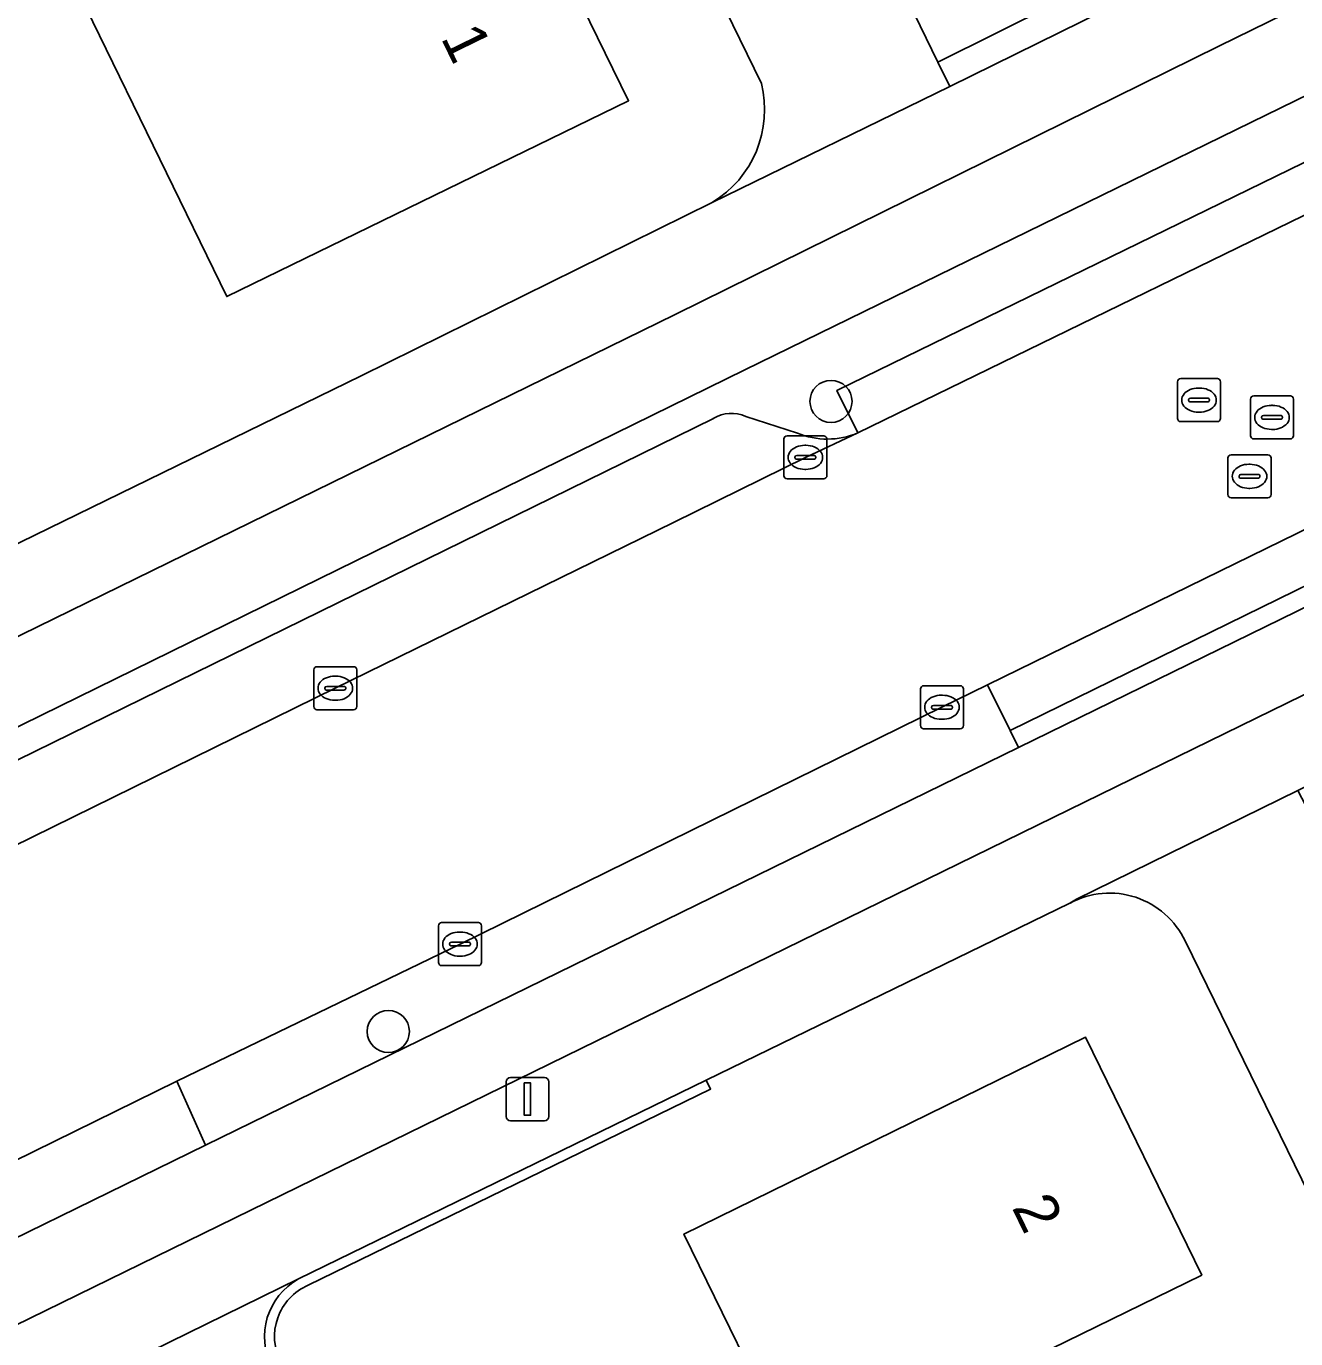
# Model space of a CAD drawing. Extents: x 160455 to 162082, y 388339 to 389736.
# Drawn here: x 160724.31 to 160753.79, y 388806.27 to 388836.74 of the extents above; entities that cross this region are included whole.
import ezdxf

# ---------------------------------------------------------------- set-up
doc = ezdxf.new("R2010")
doc.units = 0
for name, color, linetype in [('IMGEO_Berm_groen', 7, 'Continuous'), ('IMGEO_Boom', 7, 'Continuous'), ('IMGEO_Erf', 7, 'Continuous'), ('IMGEO_Fietspad_gesloten', 7, 'Continuous'), ('IMGEO_Fietspad_open', 7, 'Continuous'), ('IMGEO_Kolk', 7, 'Continuous'), ('IMGEO_Lichtmast', 7, 'Continuous'), ('IMGEO_Muur', 7, 'Continuous'), ('IMGEO_Pand', 7, 'Continuous'), ('IMGEO_Pand_nummerreeks', 7, 'Continuous'), ('IMGEO_Parkeervlak_open', 7, 'Continuous'), ('IMGEO_Rijbaan_lokaal_gesloten', 7, 'Continuous'), ('IMGEO_Rioolput', 7, 'Continuous'), ('IMGEO_Verkeerseiland_open', 7, 'Continuous'), ('IMGEO_Voetpad_open', 7, 'Continuous')]:
    doc.layers.add(name, color=color, linetype=linetype)

msp = doc.modelspace()

# ---------------------------------------------------------------- linework, layer by layer
at = {"layer": 'IMGEO_Berm_groen'}
msp.add_lwpolyline([(160747.35, 388819.997), (160747.16, 388820.393), (160746.633, 388821.448), (160745.575, 388820.932), (160734.385, 388815.434), (160727.808, 388812.252), (160728.479, 388810.767)], close=True, dxfattribs=at)
at = {"layer": 'IMGEO_Boom'}
for centre in [(160742.999, 388828.032), (160732.72, 388813.404)]:
    msp.add_circle(centre, 0.489, dxfattribs=at)
at = {"layer": 'IMGEO_Erf'}
for points in [[(160741.386, 388835.41), (160711.402, 388896.761)], [(160735.599, 388840.535), (160738.298, 388835.011), (160728.968, 388830.464), (160725.86, 388836.841)], [(160722.854, 388824.118), (160732.091, 388828.627), (160740.243, 388832.65)], [(160748.547, 388816.384), (160740.102, 388812.273), (160740.203, 388812.065), (160730.861, 388807.511)], [(160798.94, 388717.887), (160783.242, 388750), (160751.22, 388815.507)], [(160740.569, 388802.888), (160742.068, 388803.624), (160739.584, 388808.699), (160748.904, 388813.275), (160751.608, 388807.748), (160747.062, 388805.524), (160748.312, 388802.966), (160749.688, 388800.152), (160754.231, 388802.38)]]:
    msp.add_lwpolyline(points, dxfattribs=at)
for centre, radius, start, end in [((160738.931, 388834.81), 2.527, 301.27, 13.7381), ((160749.468, 388814.678), 1.938, 25.3141, 118.357), ((160731.374, 388806.321), 1.296, 113.309, 207.7642)]:
    msp.add_arc(centre, radius, start, end, dxfattribs=at)
at = {"layer": 'IMGEO_Fietspad_gesloten'}
msp.add_lwpolyline([(160935.958, 388926.245), (160935.472, 388926.041), (160929.623, 388923.115), (160929.542, 388923.081), (160924.149, 388920.448), (160820.314, 388869.678), (160812.524, 388865.895), (160804.151, 388861.828), (160752.018, 388836.29), (160739.38, 388830.051), (160696.889, 388809.242), (160688.114, 388804.953), (160688.97, 388803.215), (160707.492, 388812.318), (160716.69, 388816.833), (160716.639, 388816.936), (160723.758, 388820.418), (160723.804, 388820.325), (160740.999, 388828.766), (160761.388, 388838.743), (160804.958, 388860.084), (160820.353, 388867.581)], dxfattribs=at)
at = {"layer": 'IMGEO_Fietspad_open'}
msp.add_lwpolyline([(160814.94, 388853.077), (160807.357, 388849.403), (160800.037, 388845.82), (160791.543, 388841.683), (160784.31, 388838.109), (160774.906, 388833.514), (160767.644, 388829.959), (160760.974, 388826.661), (160747.35, 388819.997), (160728.479, 388810.767), (160721.36, 388807.285), (160701.311, 388797.443), (160693.649, 388793.713), (160694.449, 388792.087), (160749.247, 388818.903), (160815.775, 388851.461)], dxfattribs=at)
at = {"layer": 'IMGEO_Kolk'}
for p, q in [((160741.903, 388826.308), (160741.903, 388827.16)), ((160741.978, 388827.234), (160742.83, 388827.234)), ((160742.904, 388827.16), (160742.904, 388826.308)), ((160742.391, 388827.014), (160742.416, 388827.014)), ((160742.162, 388826.728), (160742.162, 388826.74)), ((160742.6, 388826.691), (160742.202, 388826.691)), ((160742.205, 388826.777), (160742.603, 388826.777)), ((160742.646, 388826.74), (160742.646, 388826.728)), ((160742.414, 388826.454), (160742.389, 388826.454)), ((160742.83, 388826.234), (160741.978, 388826.234)), ((160730.989, 388820.947), (160730.989, 388821.799)), ((160731.064, 388821.873), (160731.916, 388821.873)), ((160731.99, 388821.799), (160731.99, 388820.947)), ((160731.248, 388821.367), (160731.248, 388821.379)), ((160731.291, 388821.416), (160731.689, 388821.416)), ((160731.477, 388821.653), (160731.502, 388821.653)), ((160731.732, 388821.379), (160731.732, 388821.367)), ((160745.149, 388821.431), (160746.001, 388821.431)), ((160731.686, 388821.33), (160731.288, 388821.33)), ((160731.5, 388821.093), (160731.475, 388821.093)), ((160745.074, 388820.505), (160745.074, 388821.357)), ((160745.562, 388821.211), (160745.587, 388821.211)), ((160746.075, 388821.357), (160746.075, 388820.505)), ((160731.916, 388820.873), (160731.064, 388820.873)), ((160745.333, 388820.925), (160745.333, 388820.937)), ((160745.771, 388820.888), (160745.373, 388820.888)), ((160745.376, 388820.974), (160745.774, 388820.974)), ((160745.817, 388820.937), (160745.817, 388820.925)), ((160745.585, 388820.651), (160745.56, 388820.651)), ((160746.001, 388820.431), (160745.149, 388820.431)), ((160733.959, 388815.933), (160734.811, 388815.933)), ((160733.884, 388815.007), (160733.884, 388815.859)), ((160734.372, 388815.713), (160734.397, 388815.713)), ((160734.885, 388815.859), (160734.885, 388815.007)), ((160734.143, 388815.427), (160734.143, 388815.439)), ((160734.581, 388815.39), (160734.183, 388815.39)), ((160734.186, 388815.476), (160734.584, 388815.476)), ((160734.627, 388815.439), (160734.627, 388815.427)), ((160734.395, 388815.153), (160734.37, 388815.153)), ((160734.811, 388814.933), (160733.959, 388814.933))]:
    msp.add_line(p, q, dxfattribs=at)
for points in [[(160741.903, 388826.308), (160741.903, 388827.16)], [(160741.978, 388827.234), (160742.83, 388827.234)], [(160742.904, 388827.16), (160742.904, 388826.308)], [(160742.83, 388826.234), (160741.978, 388826.234)], [(160730.989, 388820.947), (160730.989, 388821.799)], [(160731.064, 388821.873), (160731.916, 388821.873)], [(160731.99, 388821.799), (160731.99, 388820.947)], [(160745.149, 388821.431), (160746.001, 388821.431)], [(160745.074, 388820.505), (160745.074, 388821.357)], [(160746.075, 388821.357), (160746.075, 388820.505)], [(160731.916, 388820.873), (160731.064, 388820.873)], [(160746.001, 388820.431), (160745.149, 388820.431)], [(160733.959, 388815.933), (160734.811, 388815.933)], [(160733.884, 388815.007), (160733.884, 388815.859)], [(160734.885, 388815.859), (160734.885, 388815.007)], [(160734.811, 388814.933), (160733.959, 388814.933)]]:
    msp.add_lwpolyline(points, dxfattribs=at)
for centre, radius, start, end in [((160741.98, 388827.158), 0.0765, 91.552, 178.448), ((160741.98, 388827.158), 0.0765, 91.552, 178.448), ((160742.828, 388827.158), 0.0765, 1.552, 88.448), ((160742.828, 388827.158), 0.0765, 1.552, 88.448), ((160742.202, 388826.737), 0.0403, 85.8775, 175.7526), ((160742.199, 388826.727), 0.0366, 178.938, 274.7102), ((160742.603, 388826.734), 0.043, 264.8664, 352.4533), ((160742.607, 388826.739), 0.0386, 1.7309, 96.639), ((160741.98, 388826.31), 0.0765, 181.552, 268.448), ((160741.98, 388826.31), 0.0765, 181.552, 268.448), ((160742.828, 388826.31), 0.0765, 271.552, 358.448), ((160742.828, 388826.31), 0.0765, 271.552, 358.448), ((160731.066, 388821.797), 0.0765, 91.552, 178.448), ((160731.066, 388821.797), 0.0765, 91.552, 178.448), ((160731.914, 388821.797), 0.0765, 1.552, 88.448), ((160731.914, 388821.797), 0.0765, 1.552, 88.448), ((160731.288, 388821.376), 0.0403, 85.8775, 175.7526), ((160731.285, 388821.366), 0.0366, 178.938, 274.7102), ((160731.689, 388821.373), 0.043, 264.8664, 352.4533), ((160731.693, 388821.378), 0.0386, 1.7309, 96.639), ((160745.151, 388821.355), 0.0765, 91.552, 178.448), ((160745.151, 388821.355), 0.0765, 91.552, 178.448), ((160745.999, 388821.355), 0.0765, 1.552, 88.448), ((160745.999, 388821.355), 0.0765, 1.552, 88.448), ((160731.066, 388820.949), 0.0765, 181.552, 268.448), ((160731.066, 388820.949), 0.0765, 181.552, 268.448), ((160731.914, 388820.949), 0.0765, 271.552, 358.448), ((160731.914, 388820.949), 0.0765, 271.552, 358.448), ((160745.373, 388820.934), 0.0403, 85.8775, 175.7526), ((160745.37, 388820.924), 0.0366, 178.938, 274.7102), ((160745.774, 388820.931), 0.043, 264.8664, 352.4533), ((160745.778, 388820.936), 0.0386, 1.7309, 96.639), ((160745.151, 388820.507), 0.0765, 181.552, 268.448), ((160745.151, 388820.507), 0.0765, 181.552, 268.448), ((160745.999, 388820.507), 0.0765, 271.552, 358.448), ((160745.999, 388820.507), 0.0765, 271.552, 358.448), ((160733.961, 388815.857), 0.0765, 91.552, 178.448), ((160733.961, 388815.857), 0.0765, 91.552, 178.448), ((160734.809, 388815.857), 0.0765, 1.552, 88.448), ((160734.809, 388815.857), 0.0765, 1.552, 88.448), ((160734.183, 388815.436), 0.0403, 85.8775, 175.7526), ((160734.18, 388815.426), 0.0366, 178.938, 274.7102), ((160734.584, 388815.433), 0.043, 264.8664, 352.4533), ((160734.588, 388815.438), 0.0386, 1.7309, 96.639), ((160733.961, 388815.009), 0.0765, 181.552, 268.448), ((160733.961, 388815.009), 0.0765, 181.552, 268.448), ((160734.809, 388815.009), 0.0765, 271.552, 358.448), ((160734.809, 388815.009), 0.0765, 271.552, 358.448)]:
    msp.add_arc(centre, radius, start, end, dxfattribs=at)
for centre, major_axis, ratio, start_param, end_param in [((160742.39, 388826.734), (-0.387, 0.002), 0.722429, 4.712389, 7.853982), ((160742.415, 388826.734), (-0.39, 0.002), 0.717154, 1.570796, 4.712389), ((160731.476, 388821.373), (-0.387, 0.002), 0.722429, 4.712389, 7.853982), ((160731.501, 388821.373), (-0.39, 0.002), 0.717154, 1.570796, 4.712389), ((160745.561, 388820.931), (-0.387, 0.002), 0.722429, 4.712389, 7.853982), ((160745.586, 388820.931), (-0.39, 0.002), 0.717154, 1.570796, 4.712389), ((160734.371, 388815.433), (-0.387, 0.002), 0.722429, 4.712389, 7.853982), ((160734.396, 388815.433), (-0.39, 0.002), 0.717154, 1.570796, 4.712389)]:
    msp.add_ellipse(centre, major_axis=major_axis, ratio=ratio, start_param=start_param, end_param=end_param, dxfattribs=at)
at = {"layer": 'IMGEO_Lichtmast'}
for p, q in [((160735.455, 388811.433), (160735.455, 388812.233)), ((160735.455, 388812.233), (160735.455, 388811.433)), ((160735.555, 388812.333), (160736.345, 388812.333)), ((160736.345, 388812.333), (160735.555, 388812.333)), ((160736.445, 388812.233), (160736.445, 388811.433)), ((160736.445, 388811.433), (160736.445, 388812.233)), ((160736.345, 388811.333), (160735.555, 388811.333)), ((160735.555, 388811.333), (160736.345, 388811.333))]:
    msp.add_line(p, q, dxfattribs=at)
msp.add_lwpolyline([(160735.875, 388812.208), (160736.025, 388812.208), (160736.025, 388811.458), (160735.875, 388811.458), (160735.875, 388812.208)], dxfattribs=at)
for centre, start, end in [((160735.555, 388812.233), 90, 180), ((160735.555, 388812.233), 90, 180), ((160736.345, 388812.233), 0, 90), ((160736.345, 388812.233), 360, 90), ((160735.555, 388811.433), 180, 270), ((160735.555, 388811.433), 180, 270), ((160736.345, 388811.433), 270, 0), ((160736.345, 388811.433), 270, 0)]:
    msp.add_arc(centre, 0.1, start, end, dxfattribs=at)
at = {"layer": 'IMGEO_Muur'}
for points in [[(160732.091, 388828.627), (160722.854, 388824.118)], [(160730.861, 388807.511), (160740.203, 388812.065), (160740.102, 388812.273), (160730.637, 388807.658)]]:
    msp.add_lwpolyline(points, dxfattribs=at)
for centre, radius, start, end in [((160731.373, 388806.321), 1.526, 118.8179, 207.7528), ((160731.374, 388806.321), 1.296, 113.309, 207.7642)]:
    msp.add_arc(centre, radius, start, end, dxfattribs=at)
at = {"layer": 'IMGEO_Pand'}
msp.add_lwpolyline([(160729.279, 388841.953), (160724.522, 388839.587), (160724.605, 388839.416), (160725.86, 388836.841), (160728.968, 388830.464), (160738.298, 388835.011), (160735.599, 388840.535), (160731.062, 388838.319)], close=True, dxfattribs=at)
msp.add_lwpolyline([(160740.191, 388801.433), (160741.102, 388799.571), (160741.146, 388799.481), (160748.312, 388802.966), (160747.062, 388805.524), (160751.608, 388807.748), (160748.904, 388813.275), (160739.584, 388808.699), (160742.068, 388803.624), (160740.569, 388802.888)], dxfattribs=at)
at = {"layer": 'IMGEO_Parkeervlak_open'}
for points in [[(160740.267, 388827.638), (160738.585, 388826.804), (160724.107, 388819.706), (160716.991, 388816.218), (160707.533, 388811.581), (160702.657, 388809.195)], [(160742.219, 388827.295), (160741.018, 388827.682)], [(160700.991, 388806.404), (160700.822, 388806.3), (160701.76, 388806.77), (160706.188, 388808.94), (160731.49, 388821.372), (160739.341, 388825.221), (160742.405, 388826.733), (160743.619, 388827.3)], [(160730.637, 388807.658), (160722.48, 388803.659)]]:
    msp.add_lwpolyline(points, dxfattribs=at)
for centre, radius, start, end in [((160740.685, 388826.931), 0.822, 66.1049, 120.6011), ((160742.913, 388828.971), 1.814, 247.5058, 292.9035), ((160731.373, 388806.321), 1.526, 118.8179, 207.7528)]:
    msp.add_arc(centre, radius, start, end, dxfattribs=at)
at = {"layer": 'IMGEO_Rijbaan_lokaal_gesloten'}
for points in [[(160701.48, 388925.903), (160702.171, 388924.594), (160714.987, 388898.304), (160717.72, 388892.699), (160718.927, 388890.222), (160722.821, 388882.237), (160725.648, 388876.442), (160727.942, 388871.738), (160730.503, 388866.526), (160733.518, 388860.392), (160735.965, 388855.414), (160738.64, 388849.931), (160741.656, 388843.751), (160743.781, 388839.396), (160745.065, 388836.754), (160745.48, 388835.906), (160749.558, 388837.942), (160749.315, 388838.459), (160747.718, 388841.637), (160740.066, 388857.393), (160733.637, 388870.475), (160732.064, 388873.676), (160730.834, 388876.19), (160725.78, 388886.522)], [(160757.309, 388833.976), (160743.619, 388827.3), (160742.405, 388826.733), (160739.341, 388825.221), (160731.49, 388821.372), (160706.188, 388808.94), (160701.76, 388806.77), (160700.822, 388806.3), (160700.703, 388806.24), (160703.586, 388800.369), (160705.59, 388801.342), (160720.422, 388808.602), (160720.692, 388808.751), (160727.808, 388812.252), (160734.385, 388815.434), (160745.575, 388820.932), (160746.633, 388821.448), (160760.283, 388828.134)]]:
    msp.add_lwpolyline(points, dxfattribs=at)
at = {"layer": 'IMGEO_Rioolput'}
for p, q in [((160751.042, 388827.637), (160751.042, 388828.489)), ((160751.117, 388828.563), (160751.969, 388828.563)), ((160752.043, 388828.489), (160752.043, 388827.637)), ((160751.301, 388828.057), (160751.301, 388828.069)), ((160751.344, 388828.106), (160751.742, 388828.106)), ((160751.53, 388828.343), (160751.555, 388828.343)), ((160751.785, 388828.069), (160751.785, 388828.057)), ((160752.737, 388827.235), (160752.737, 388828.087)), ((160752.812, 388828.161), (160753.664, 388828.161)), ((160753.738, 388828.087), (160753.738, 388827.235)), ((160751.739, 388828.02), (160751.341, 388828.02)), ((160751.553, 388827.783), (160751.528, 388827.783)), ((160753.225, 388827.941), (160753.25, 388827.941)), ((160751.969, 388827.563), (160751.117, 388827.563)), ((160752.996, 388827.655), (160752.996, 388827.667)), ((160753.434, 388827.618), (160753.036, 388827.618)), ((160753.039, 388827.704), (160753.437, 388827.704)), ((160753.48, 388827.667), (160753.48, 388827.655)), ((160753.664, 388827.161), (160752.812, 388827.161)), ((160753.248, 388827.381), (160753.223, 388827.381)), ((160752.215, 388825.867), (160752.215, 388826.719)), ((160752.29, 388826.793), (160753.142, 388826.793)), ((160752.703, 388826.573), (160752.728, 388826.573)), ((160753.216, 388826.719), (160753.216, 388825.867)), ((160752.474, 388826.287), (160752.474, 388826.299)), ((160752.912, 388826.25), (160752.514, 388826.25)), ((160752.517, 388826.336), (160752.915, 388826.336)), ((160752.958, 388826.299), (160752.958, 388826.287)), ((160752.726, 388826.013), (160752.701, 388826.013)), ((160753.142, 388825.793), (160752.29, 388825.793))]:
    msp.add_line(p, q, dxfattribs=at)
for points in [[(160751.042, 388827.637), (160751.042, 388828.489)], [(160751.117, 388828.563), (160751.969, 388828.563)], [(160752.043, 388828.489), (160752.043, 388827.637)], [(160752.737, 388827.235), (160752.737, 388828.087)], [(160752.812, 388828.161), (160753.664, 388828.161)], [(160753.738, 388828.087), (160753.738, 388827.235)], [(160751.969, 388827.563), (160751.117, 388827.563)], [(160753.664, 388827.161), (160752.812, 388827.161)], [(160752.215, 388825.867), (160752.215, 388826.719)], [(160752.29, 388826.793), (160753.142, 388826.793)], [(160753.216, 388826.719), (160753.216, 388825.867)], [(160753.142, 388825.793), (160752.29, 388825.793)]]:
    msp.add_lwpolyline(points, dxfattribs=at)
for centre, radius, start, end in [((160751.119, 388828.487), 0.0765, 91.552, 178.448), ((160751.119, 388828.487), 0.0765, 91.552, 178.448), ((160751.967, 388828.487), 0.0765, 1.552, 88.448), ((160751.967, 388828.487), 0.0765, 1.552, 88.448), ((160751.341, 388828.066), 0.0403, 85.8775, 175.7526), ((160751.746, 388828.068), 0.0386, 1.7309, 96.639), ((160752.814, 388828.085), 0.0765, 91.552, 178.448), ((160752.814, 388828.085), 0.0765, 91.552, 178.448), ((160753.662, 388828.085), 0.0765, 1.552, 88.448), ((160753.662, 388828.085), 0.0765, 1.552, 88.448), ((160751.338, 388828.056), 0.0366, 178.938, 274.7102), ((160751.742, 388828.063), 0.043, 264.8664, 352.4533), ((160751.119, 388827.639), 0.0765, 181.552, 268.448), ((160751.119, 388827.639), 0.0765, 181.552, 268.448), ((160751.967, 388827.639), 0.0765, 271.552, 358.448), ((160751.967, 388827.639), 0.0765, 271.552, 358.448), ((160753.036, 388827.664), 0.0403, 85.8775, 175.7526), ((160753.033, 388827.654), 0.0366, 178.938, 274.7102), ((160753.437, 388827.661), 0.043, 264.8664, 352.4533), ((160753.441, 388827.666), 0.0386, 1.7309, 96.639), ((160752.814, 388827.237), 0.0765, 181.552, 268.448), ((160752.814, 388827.237), 0.0765, 181.552, 268.448), ((160753.662, 388827.237), 0.0765, 271.552, 358.448), ((160753.662, 388827.237), 0.0765, 271.552, 358.448), ((160752.292, 388826.717), 0.0765, 91.552, 178.448), ((160752.292, 388826.717), 0.0765, 91.552, 178.448), ((160753.14, 388826.717), 0.0765, 1.552, 88.448), ((160753.14, 388826.717), 0.0765, 1.552, 88.448), ((160752.514, 388826.296), 0.0403, 85.8775, 175.7526), ((160752.511, 388826.286), 0.0366, 178.938, 274.7102), ((160752.915, 388826.293), 0.043, 264.8664, 352.4533), ((160752.919, 388826.298), 0.0386, 1.7309, 96.639), ((160752.292, 388825.869), 0.0765, 181.552, 268.448), ((160752.292, 388825.869), 0.0765, 181.552, 268.448), ((160753.14, 388825.869), 0.0765, 271.552, 358.448), ((160753.14, 388825.869), 0.0765, 271.552, 358.448)]:
    msp.add_arc(centre, radius, start, end, dxfattribs=at)
for centre, major_axis, ratio, start_param, end_param in [((160751.529, 388828.063), (-0.387, 0.002), 0.722429, 4.712389, 7.853982), ((160751.554, 388828.063), (-0.39, 0.002), 0.717154, 1.570796, 4.712389), ((160753.224, 388827.661), (-0.387, 0.002), 0.722429, 4.712389, 7.853982), ((160753.249, 388827.661), (-0.39, 0.002), 0.717154, 1.570796, 4.712389), ((160752.702, 388826.293), (-0.387, 0.002), 0.722429, 4.712389, 7.853982), ((160752.727, 388826.293), (-0.39, 0.002), 0.717154, 1.570796, 4.712389)]:
    msp.add_ellipse(centre, major_axis=major_axis, ratio=ratio, start_param=start_param, end_param=end_param, dxfattribs=at)
at = {"layer": 'IMGEO_Verkeerseiland_open'}
for points in [[(160902.415, 388905.053), (160903.765, 388905.697), (160903.541, 388906.153), (160910.727, 388909.682), (160909.887, 388911.468), (160820.353, 388867.581), (160804.958, 388860.084), (160761.388, 388838.743), (160740.999, 388828.766), (160723.804, 388820.325), (160724.107, 388819.706), (160738.585, 388826.804), (160740.267, 388827.638)], [(160743.619, 388827.3), (160743.137, 388828.289), (160756.827, 388834.965), (160757.309, 388833.976), (160759.446, 388835.039)], [(160741.018, 388827.682), (160742.219, 388827.295)]]:
    msp.add_lwpolyline(points, dxfattribs=at)
for points in [[(160757.309, 388833.976), (160756.827, 388834.965), (160743.137, 388828.289), (160743.619, 388827.3)], [(160760.283, 388828.134), (160746.633, 388821.448), (160747.16, 388820.393), (160760.774, 388827.06)], [(160760.774, 388827.06), (160747.16, 388820.393), (160747.35, 388819.997), (160760.974, 388826.661)], [(160727.808, 388812.252), (160720.692, 388808.751), (160721.36, 388807.285), (160728.479, 388810.767)]]:
    msp.add_lwpolyline(points, close=True, dxfattribs=at)
for centre, radius, start, end in [((160740.685, 388826.931), 0.822, 66.1049, 120.6011), ((160742.913, 388828.971), 1.814, 247.5058, 292.9035)]:
    msp.add_arc(centre, radius, start, end, dxfattribs=at)
at = {"layer": 'IMGEO_Voetpad_open'}
for points in [[(160701.075, 388922.662), (160699.17, 388921.78), (160711.402, 388896.761), (160741.386, 388835.41)], [(160755.104, 388839.929), (160749.832, 388837.359), (160745.755, 388835.344), (160740.243, 388832.65), (160732.091, 388828.627), (160722.854, 388824.118), (160714.616, 388820.104), (160705.134, 388815.433), (160696.811, 388811.38), (160691.333, 388808.709), (160687.247, 388806.714), (160688.114, 388804.953), (160696.889, 388809.242), (160739.38, 388830.051), (160752.018, 388836.29), (160804.151, 388861.828)], [(160815.775, 388851.461), (160749.247, 388818.903), (160694.449, 388792.087), (160695.296, 388790.366), (160699.413, 388792.355), (160704.759, 388794.962), (160713.096, 388799.04), (160722.48, 388803.659), (160730.637, 388807.658), (160740.102, 388812.273), (160748.547, 388816.384), (160748.7, 388816.472), (160753.839, 388819.002), (160757.844, 388820.96), (160763.253, 388823.601), (160814.32, 388848.575)], [(160740.243, 388832.65), (160745.755, 388835.344), (160745.48, 388835.906), (160745.065, 388836.754)], [(160754.12, 388818.451), (160753.839, 388819.002), (160748.7, 388816.472), (160748.547, 388816.384)], [(160751.22, 388815.507), (160783.242, 388750), (160798.94, 388717.887), (160796.193, 388716.592), (160796.096, 388716.524), (160796.229, 388716.231), (160787.552, 388711.973), (160789.992, 388706.936), (160811.085, 388717.249), (160809.661, 388720.335), (160800.591, 388722.19), (160796.035, 388731.513), (160796.496, 388731.738)]]:
    msp.add_lwpolyline(points, dxfattribs=at)
msp.add_lwpolyline([(160745.48, 388835.906), (160745.755, 388835.344), (160749.832, 388837.359), (160749.558, 388837.942)], close=True, dxfattribs=at)
for centre, radius, start, end in [((160738.931, 388834.81), 2.527, 301.27, 13.7381), ((160749.468, 388814.678), 1.938, 25.3141, 118.357)]:
    msp.add_arc(centre, radius, start, end, dxfattribs=at)

# ---------------------------------------------------------------- texts
at = {"layer": 'IMGEO_Pand_nummerreeks'}
for s, rotation, p in [('1', 296.0407, (160733.93, 388836.478)), ('2', 296.0695, (160747.188, 388809.319))]:
    msp.add_text(s, height=1, rotation=rotation, dxfattribs=at).set_placement(p)

doc.saveas('drawing.dxf')
